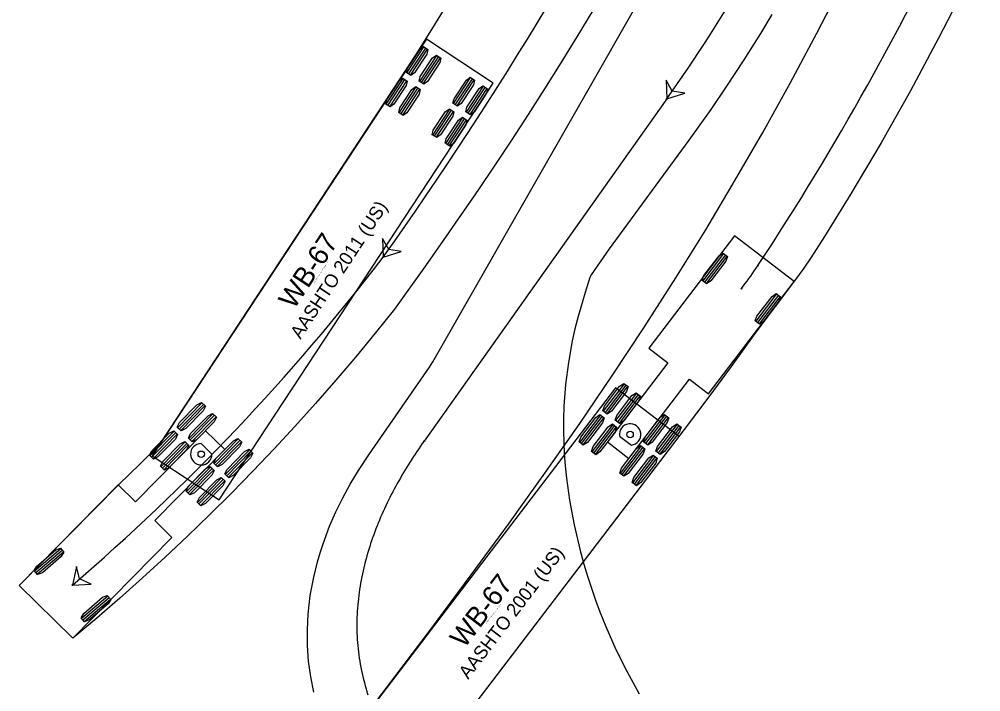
# Model space of a CAD drawing. Extents: x 2175591 to 2194071, y 76570 to 86955.
# Drawn here: x 2192827.4 to 2192929.6, y 86431.1 to 86502.5 of the extents above; entities that cross this region are included whole.
import ezdxf

# ---------------------------------------------------------------- set-up
doc = ezdxf.new("R2010")
doc.units = 0
doc.layers.add('-NOPLT', color=7, linetype='Continuous')
doc.layers.add('C-UTIL-STRM-TEXT', color=7, linetype='Continuous')

msp = doc.modelspace()

# ---------------------------------------------------------------- linework, layer by layer
at = {"layer": '-NOPLT'}
for p, q in [((2192870.68, 86500.42), (2192841.55, 86456.15)), ((2192868.59, 86496.83), (2192870.41, 86499.59)), ((2192877.78, 86495.75), (2192870.68, 86500.42)), ((2192868.78, 86496.71), (2192870.6, 86499.46)), ((2192868.98, 86496.58), (2192870.79, 86499.34)), ((2192869.97, 86495.92), (2192871.79, 86498.68)), ((2192870.16, 86495.8), (2192871.98, 86498.56)), ((2192870.35, 86495.67), (2192872.17, 86498.43)), ((2192848.65, 86451.48), (2192877.78, 86495.75)), ((2192866.39, 86493.49), (2192868.21, 86496.25)), ((2192866.59, 86493.36), (2192868.4, 86496.12)), ((2192866.78, 86493.24), (2192868.59, 86496)), ((2192873.55, 86493.57), (2192875.36, 86496.33)), ((2192873.74, 86493.44), (2192875.56, 86496.2)), ((2192873.93, 86493.32), (2192875.75, 86496.08)), ((2192874.93, 86492.66), (2192876.74, 86495.42)), ((2192867.77, 86492.58), (2192869.59, 86495.34)), ((2192867.96, 86492.46), (2192869.78, 86495.21)), ((2192868.16, 86492.33), (2192869.97, 86495.09)), ((2192875.12, 86492.54), (2192876.93, 86495.29)), ((2192875.31, 86492.41), (2192877.13, 86495.17)), ((2192896.22, 86494.08), (2192870.43, 86457.71)), ((2192871.35, 86490.23), (2192873.17, 86492.99)), ((2192871.54, 86490.1), (2192873.36, 86492.86)), ((2192871.73, 86489.98), (2192873.55, 86492.73)), ((2192872.73, 86489.32), (2192874.54, 86492.08)), ((2192872.92, 86489.2), (2192874.73, 86491.95)), ((2192873.11, 86489.07), (2192874.93, 86491.83)), ((2192844.25, 86459.15), (2192846.82, 86461.77)), ((2192844.41, 86458.99), (2192846.99, 86461.61)), ((2192844.58, 86458.83), (2192847.15, 86461.45)), ((2192845.43, 86458), (2192848, 86460.61)), ((2192845.59, 86457.84), (2192848.16, 86460.45)), ((2192845.75, 86457.68), (2192848.33, 86460.29)), ((2192847.2, 86458.82), (2192839.77, 86451.27)), ((2192841.3, 86456.16), (2192843.88, 86458.77)), ((2192849.25, 86456.81), (2192847.2, 86458.82)), ((2192841.47, 86456), (2192844.04, 86458.61)), ((2192841.63, 86455.84), (2192844.2, 86458.45)), ((2192842.48, 86455), (2192845.05, 86457.62)), ((2192848.12, 86455.34), (2192850.69, 86457.96)), ((2192848.29, 86455.18), (2192850.86, 86457.79)), ((2192848.45, 86455.02), (2192851.02, 86457.63)), ((2192841.81, 86449.26), (2192849.25, 86456.81)), ((2192842.64, 86454.84), (2192845.22, 86457.46)), ((2192842.81, 86454.68), (2192845.38, 86457.3)), ((2192847.89, 86456.33), (2192846.74, 86457.46)), ((2192849.3, 86454.18), (2192851.87, 86456.8)), ((2192849.46, 86454.02), (2192852.03, 86456.64)), ((2192841.55, 86456.15), (2192848.65, 86451.48)), ((2192849.62, 86453.86), (2192852.2, 86456.48)), ((2192845.18, 86452.35), (2192847.75, 86454.96)), ((2192845.34, 86452.19), (2192847.91, 86454.8)), ((2192845.5, 86452.03), (2192848.07, 86454.64)), ((2192846.35, 86451.19), (2192848.92, 86453.8)), ((2192846.51, 86451.03), (2192849.09, 86453.64)), ((2192837.94, 86453.07), (2192827.41, 86442.38)), ((2192839.77, 86451.27), (2192837.94, 86453.07)), ((2192846.68, 86450.87), (2192849.25, 86453.48)), ((2192848.65, 86451.48), (2192848.65, 86451.48)), ((2192843.64, 86447.46), (2192841.81, 86449.26)), ((2192833.11, 86436.77), (2192843.64, 86447.46)), ((2192829.03, 86443.92), (2192831.82, 86446.3)), ((2192829.18, 86443.74), (2192831.97, 86446.13)), ((2192829.33, 86443.57), (2192832.12, 86445.95)), ((2192827.41, 86442.38), (2192833.11, 86436.77)), ((2192834.02, 86438.89), (2192836.81, 86441.28)), ((2192834.17, 86438.72), (2192836.96, 86441.11)), ((2192834.32, 86438.55), (2192837.11, 86440.93)), ((2192833.11, 86436.77), (2192833.11, 86436.77))]:
    msp.add_line(p, q, dxfattribs=at)
for points in [[(2192858.7, 86431.03), (2192858.38, 86432.67), (2192858.16, 86434.32), (2192858.04, 86435.98), (2192858.03, 86437.65), (2192858.11, 86439.31), (2192858.21, 86440.31), (2192858.34, 86441.3), (2192858.7, 86443.26), (2192859.1, 86444.88), (2192859.38, 86445.84), (2192859.69, 86446.79), (2192860.39, 86448.66), (2192861.06, 86450.19), (2192861.79, 86451.69), (2192862.59, 86453.15), (2192863.45, 86454.58), (2192864.55, 86456.25), (2192871, 86465.57), (2192871.35, 86466.14), (2192896.64, 86510.42)], [(2192888.35, 86503.45), (2192886.66, 86500.67), (2192884.96, 86497.9), (2192883.23, 86495.15), (2192881.48, 86492.41), (2192879.71, 86489.68), (2192877.89, 86486.93), (2192876.2, 86484.45), (2192872.46, 86479.03), (2192870.59, 86476.34), (2192867.29, 86471.72), (2192865.25, 86469.17), (2192863.17, 86466.66), (2192861.05, 86464.17), (2192858.9, 86461.71), (2192856.71, 86459.28), (2192854.49, 86456.89), (2192852.24, 86454.52), (2192849.96, 86452.19), (2192847.64, 86449.88), (2192845.3, 86447.61), (2192842.92, 86445.38), (2192840.52, 86443.18), (2192838.09, 86441.02), (2192835.65, 86438.91), (2192833.11, 86436.77), (2192827.41, 86442.38), (2192837.98, 86453.11), (2192840.26, 86455.28), (2192842.22, 86457.21), (2192842.46, 86457.52), (2192869.6, 86498.8), (2192871.26, 86501.43), (2192872.89, 86504.08)], [(2192907.38, 86503.03), (2192906.18, 86501.03), (2192904.41, 86498.21), (2192902.58, 86495.42), (2192900.89, 86492.94), (2192898.57, 86489.68), (2192890.1, 86478.12), (2192888.2, 86475.38), (2192888.05, 86475.09), (2192887.53, 86473.5), (2192886.79, 86470.94), (2192886.46, 86469.65), (2192886.17, 86468.35), (2192885.76, 86466.05), (2192885.46, 86463.74), (2192885.28, 86461.41), (2192885.24, 86460.08), (2192885.23, 86458.75), (2192885.32, 86456.41), (2192885.41, 86455.08), (2192885.55, 86453.76), (2192885.87, 86451.45), (2192886.36, 86448.83), (2192886.98, 86446.23), (2192887.42, 86444.63), (2192887.81, 86443.35), (2192888.66, 86440.82), (2192889.12, 86439.57), (2192889.74, 86438.03), (2192890.82, 86435.59), (2192892, 86433.2), (2192893.29, 86430.86)], [(2192896.22, 86494.08), (2192898.13, 86494.67), (2192896.8, 86494.89), (2192896.15, 86496.07), (2192896.22, 86494.08)], [(2192870.43, 86457.71), (2192870.24, 86457.44), (2192870.05, 86457.17), (2192869.86, 86456.89), (2192869.67, 86456.62), (2192869.49, 86456.34), (2192869.31, 86456.06), (2192869.13, 86455.78), (2192868.95, 86455.5), (2192868.77, 86455.22), (2192868.59, 86454.93), (2192868.42, 86454.65), (2192868.25, 86454.36), (2192868.08, 86454.08), (2192867.91, 86453.79), (2192867.75, 86453.5), (2192867.58, 86453.21), (2192867.42, 86452.91), (2192867.26, 86452.62), (2192867.11, 86452.33), (2192866.95, 86452.03), (2192866.8, 86451.73), (2192866.65, 86451.44), (2192866.51, 86451.14), (2192866.36, 86450.84), (2192866.22, 86450.53), (2192866.08, 86450.23), (2192865.95, 86449.93), (2192865.81, 86449.62), (2192865.68, 86449.31), (2192865.56, 86449.01), (2192865.43, 86448.7), (2192865.31, 86448.39), (2192865.19, 86448.08), (2192865.08, 86447.76), (2192864.96, 86447.45), (2192864.85, 86447.13), (2192864.75, 86446.82), (2192864.65, 86446.5), (2192864.55, 86446.18), (2192864.45, 86445.86), (2192864.36, 86445.54), (2192864.27, 86445.22), (2192864.18, 86444.9), (2192864.1, 86444.58), (2192864.02, 86444.25), (2192863.95, 86443.93), (2192863.88, 86443.6), (2192863.81, 86443.28), (2192863.75, 86442.95), (2192863.69, 86442.62), (2192863.63, 86442.29), (2192863.58, 86441.96), (2192863.53, 86441.63), (2192863.49, 86441.3), (2192863.45, 86440.97), (2192863.41, 86440.64), (2192863.38, 86440.31), (2192863.35, 86439.98), (2192863.33, 86439.64), (2192863.31, 86439.31), (2192863.3, 86438.98), (2192863.29, 86438.64), (2192863.29, 86438.31), (2192863.29, 86437.98), (2192863.29, 86437.64), (2192863.3, 86437.31), (2192863.31, 86436.98), (2192863.33, 86436.64), (2192863.35, 86436.31), (2192863.38, 86435.98), (2192863.41, 86435.65), (2192863.45, 86435.32), (2192863.49, 86434.99), (2192863.54, 86434.66), (2192863.59, 86434.33), (2192863.65, 86434), (2192863.71, 86433.67), (2192863.78, 86433.34), (2192863.85, 86433.02), (2192863.92, 86432.69), (2192864.01, 86432.37), (2192864.09, 86432.05), (2192864.18, 86431.73), (2192864.27, 86431.41), (2192864.36, 86431.09), (2192864.46, 86430.77)]]:
    msp.add_lwpolyline(points, dxfattribs=at)
for points in [[(2192869.02, 86496.55), (2192868.55, 86496.86), (2192868.66, 86497.34), (2192869.96, 86499.33), (2192870.36, 86499.62), (2192870.84, 86499.31), (2192870.73, 86498.82), (2192869.42, 86496.84)], [(2192870.4, 86495.64), (2192869.92, 86495.96), (2192870.03, 86496.44), (2192871.34, 86498.42), (2192871.74, 86498.71), (2192872.22, 86498.4), (2192872.11, 86497.92), (2192870.8, 86495.93)], [(2192866.82, 86493.21), (2192866.35, 86493.52), (2192866.46, 86494), (2192867.76, 86495.99), (2192868.16, 86496.28), (2192868.64, 86495.96), (2192868.53, 86495.48), (2192867.22, 86493.5)], [(2192873.98, 86493.29), (2192873.5, 86493.6), (2192873.61, 86494.08), (2192874.92, 86496.07), (2192875.32, 86496.36), (2192875.79, 86496.04), (2192875.68, 86495.56), (2192874.38, 86493.58)], [(2192875.36, 86492.38), (2192874.88, 86492.69), (2192874.99, 86493.18), (2192876.3, 86495.16), (2192876.69, 86495.45), (2192877.17, 86495.14), (2192877.06, 86494.66), (2192875.76, 86492.67)], [(2192896.22, 86494.08), (2192898.13, 86494.67), (2192896.8, 86494.89), (2192896.15, 86496.07)], [(2192868.2, 86492.3), (2192867.73, 86492.61), (2192867.84, 86493.1), (2192869.14, 86495.08), (2192869.54, 86495.37), (2192870.02, 86495.06), (2192869.91, 86494.58), (2192868.6, 86492.59)], [(2192871.78, 86489.95), (2192871.3, 86490.26), (2192871.41, 86490.74), (2192872.72, 86492.73), (2192873.12, 86493.02), (2192873.6, 86492.7), (2192873.49, 86492.22), (2192872.18, 86490.24)], [(2192873.16, 86489.04), (2192872.68, 86489.35), (2192872.79, 86489.83), (2192874.1, 86491.82), (2192874.5, 86492.11), (2192874.97, 86491.8), (2192874.86, 86491.32), (2192873.56, 86489.33)], [(2192866.09, 86477.25), (2192868, 86477.84), (2192866.67, 86478.07), (2192866.02, 86479.25)], [(2192844.62, 86458.79), (2192844.21, 86459.19), (2192844.45, 86459.68), (2192846.3, 86461.56), (2192846.78, 86461.81), (2192847.19, 86461.41), (2192846.95, 86460.92), (2192845.1, 86459.04)], [(2192845.79, 86457.64), (2192845.39, 86458.04), (2192845.62, 86458.52), (2192847.48, 86460.4), (2192847.96, 86460.65), (2192848.37, 86460.25), (2192848.13, 86459.76), (2192846.28, 86457.88)], [(2192841.67, 86455.8), (2192841.26, 86456.2), (2192841.5, 86456.69), (2192843.35, 86458.57), (2192843.84, 86458.81), (2192844.24, 86458.41), (2192844.01, 86457.93), (2192842.15, 86456.05)], [(2192842.85, 86454.64), (2192842.44, 86455.04), (2192842.68, 86455.53), (2192844.53, 86457.41), (2192845.01, 86457.66), (2192845.42, 86457.26), (2192845.18, 86456.77), (2192843.33, 86454.89)], [(2192848.49, 86454.98), (2192848.08, 86455.38), (2192848.32, 86455.87), (2192850.17, 86457.75), (2192850.65, 86458), (2192851.06, 86457.59), (2192850.82, 86457.11), (2192848.97, 86455.23)], [(2192849.67, 86453.82), (2192849.26, 86454.22), (2192849.49, 86454.71), (2192851.35, 86456.59), (2192851.83, 86456.84), (2192852.24, 86456.44), (2192852, 86455.95), (2192850.15, 86454.07)], [(2192845.54, 86451.99), (2192845.14, 86452.39), (2192845.37, 86452.88), (2192847.22, 86454.76), (2192847.71, 86455), (2192848.12, 86454.6), (2192847.88, 86454.11), (2192846.03, 86452.23)], [(2192846.72, 86450.83), (2192846.31, 86451.23), (2192846.55, 86451.72), (2192848.4, 86453.6), (2192848.88, 86453.84), (2192849.29, 86453.44), (2192849.05, 86452.96), (2192847.2, 86451.08)], [(2192829.37, 86443.53), (2192828.99, 86443.96), (2192829.27, 86444.43), (2192831.28, 86446.14), (2192831.78, 86446.34), (2192832.15, 86445.91), (2192831.88, 86445.44), (2192829.87, 86443.73)], [(2192833.07, 86442.42), (2192835.07, 86442.53), (2192833.83, 86443.07), (2192833.48, 86444.38)], [(2192834.36, 86438.5), (2192833.99, 86438.94), (2192834.26, 86439.4), (2192836.27, 86441.12), (2192836.77, 86441.32), (2192837.14, 86440.89), (2192836.86, 86440.42), (2192834.86, 86438.71)]]:
    msp.add_lwpolyline(points, close=True, dxfattribs=at)
for centre, radius in [((2192896.22, 86494.08), 0.0417), ((2192896.22, 86494.08), 0.0417), ((2192866.09, 86477.25), 0.0417), ((2192866.09, 86477.25), 0.0417), ((2192870.43, 86457.71), 0.0417), ((2192870.43, 86457.71), 0.0417), ((2192846.75, 86456.32), 0.34), ((2192833.07, 86442.42), 0.0417)]:
    msp.add_circle(centre, radius, dxfattribs=at)
for centre, radius, start, end in [((2192518.8, 86723.56), 425.77, 324.656, 333.1974), ((2192758.86, 86591.64), 168.49, 324.6149, 330.0297), ((2192682.44, 86618.31), 231.57, 310.5753, 322.4721), ((2192846.75, 86456.32), 1.14, 90.4434, 0.4434)]:
    msp.add_arc(centre, radius, start, end, dxfattribs=at)
at = {"layer": 'C-UTIL-STRM-TEXT'}
for p, q in [((2192903.4, 86479.52), (2192894.3, 86467.59)), ((2192909.76, 86474.66), (2192903.4, 86479.52)), ((2192903.4, 86479.52), (2192903.4, 86479.52)), ((2192902.26, 86477.65), (2192900.04, 86474.74)), ((2192902.45, 86477.51), (2192900.22, 86474.6)), ((2192902.63, 86477.38), (2192900.4, 86474.46)), ((2192900.66, 86462.74), (2192909.76, 86474.66)), ((2192907.89, 86473.36), (2192905.67, 86470.44)), ((2192908.08, 86473.22), (2192905.85, 86470.3)), ((2192908.26, 86473.08), (2192906.03, 86470.16)), ((2192894.3, 86467.59), (2192896.34, 86466.03)), ((2192896.34, 86466.03), (2192889.92, 86457.62)), ((2192891.7, 86463.81), (2192889.47, 86460.89)), ((2192892.19, 86455.88), (2192898.62, 86464.29)), ((2192898.62, 86464.29), (2192900.66, 86462.74)), ((2192890.76, 86463.37), (2192858.61, 86421.24)), ((2192891.88, 86463.67), (2192889.66, 86460.75)), ((2192892.06, 86463.53), (2192889.84, 86460.62)), ((2192897.52, 86458.21), (2192890.76, 86463.37)), ((2192890.76, 86463.37), (2192890.76, 86463.37)), ((2192893.01, 86462.81), (2192890.78, 86459.89)), ((2192893.19, 86462.67), (2192890.97, 86459.75)), ((2192893.37, 86462.53), (2192891.15, 86459.61)), ((2192889.17, 86460.5), (2192886.95, 86457.58)), ((2192889.35, 86460.36), (2192887.13, 86457.44)), ((2192889.53, 86460.22), (2192887.31, 86457.3)), ((2192896.02, 86460.51), (2192893.79, 86457.6)), ((2192896.2, 86460.37), (2192893.97, 86457.46)), ((2192896.38, 86460.23), (2192894.16, 86457.32)), ((2192890.48, 86459.49), (2192888.26, 86456.58)), ((2192890.66, 86459.36), (2192888.44, 86456.44)), ((2192890.85, 86459.22), (2192888.62, 86456.3)), ((2192897.33, 86459.51), (2192895.1, 86456.6)), ((2192897.51, 86459.37), (2192895.29, 86456.46)), ((2192897.69, 86459.23), (2192895.47, 86456.32)), ((2192865.36, 86416.08), (2192897.52, 86458.21)), ((2192889.92, 86457.62), (2192892.19, 86455.88)), ((2192891.19, 86458.25), (2192892.47, 86457.27)), ((2192893.49, 86457.2), (2192891.26, 86454.28)), ((2192893.67, 86457.06), (2192891.45, 86454.15)), ((2192893.85, 86456.92), (2192891.63, 86454.01)), ((2192894.8, 86456.2), (2192892.58, 86453.28)), ((2192894.98, 86456.06), (2192892.76, 86453.14)), ((2192895.17, 86455.92), (2192892.94, 86453.01))]:
    msp.add_line(p, q, dxfattribs=at)
for points in [[(2192861.46, 86419.09), (2192858.81, 86421.11), (2192858.76, 86421.44), (2192866.44, 86431.51), (2192871.07, 86437.62), (2192875.45, 86443.5), (2192879.39, 86448.88), (2192883.27, 86454.3), (2192886.9, 86459.49), (2192890.46, 86464.72), (2192893.77, 86469.73), (2192897.19, 86475.06), (2192900.35, 86480.16), (2192903.43, 86485.31), (2192906.42, 86490.51), (2192909.34, 86495.75), (2192912.16, 86501.05), (2192914.74, 86506.09)], [(2192927.99, 86506.14), (2192925.1, 86500.51), (2192922.1, 86494.93), (2192918.99, 86489.41), (2192915.76, 86483.97), (2192912.96, 86479.43), (2192911.53, 86477.18), (2192910.79, 86476.07), (2192909.8, 86474.73), (2192905.56, 86469.16), (2192903.05, 86465.63), (2192900.68, 86462.41), (2192898.08, 86458.95), (2192865.53, 86416.3), (2192864.91, 86416.47), (2192861.46, 86419.09)], [(2192904.15, 86473.91), (2192904.35, 86474.17), (2192904.55, 86474.44), (2192904.75, 86474.71), (2192904.95, 86474.98), (2192905.14, 86475.25), (2192905.33, 86475.52), (2192905.52, 86475.8), (2192905.71, 86476.07), (2192905.89, 86476.35)]]:
    msp.add_lwpolyline(points, dxfattribs=at)
for points in [[(2192902.22, 86477.69), (2192902.67, 86477.34), (2192902.5, 86476.83), (2192900.9, 86474.73), (2192900.45, 86474.43), (2192899.99, 86474.77), (2192900.17, 86475.29), (2192901.77, 86477.38)], [(2192907.85, 86473.39), (2192908.3, 86473.04), (2192908.13, 86472.53), (2192906.53, 86470.43), (2192906.08, 86470.13), (2192905.62, 86470.48), (2192905.8, 86470.99), (2192907.4, 86473.09)], [(2192891.65, 86463.84), (2192892.11, 86463.5), (2192891.93, 86462.98), (2192890.33, 86460.88), (2192889.88, 86460.58), (2192889.43, 86460.93), (2192889.6, 86461.44), (2192891.2, 86463.54)], [(2192892.96, 86462.84), (2192893.42, 86462.49), (2192893.24, 86461.98), (2192891.64, 86459.88), (2192891.19, 86459.58), (2192890.74, 86459.93), (2192890.91, 86460.44), (2192892.52, 86462.54)], [(2192889.12, 86460.53), (2192889.58, 86460.18), (2192889.4, 86459.67), (2192887.8, 86457.57), (2192887.35, 86457.27), (2192886.9, 86457.62), (2192887.07, 86458.13), (2192888.68, 86460.23)], [(2192895.97, 86460.55), (2192896.43, 86460.2), (2192896.25, 86459.69), (2192894.65, 86457.59), (2192894.2, 86457.28), (2192893.75, 86457.63), (2192893.92, 86458.14), (2192895.52, 86460.24)], [(2192890.44, 86459.53), (2192890.89, 86459.18), (2192890.72, 86458.67), (2192889.11, 86456.57), (2192888.67, 86456.27), (2192888.21, 86456.61), (2192888.39, 86457.13), (2192889.99, 86459.23)], [(2192897.28, 86459.55), (2192897.74, 86459.2), (2192897.56, 86458.69), (2192895.96, 86456.59), (2192895.51, 86456.28), (2192895.06, 86456.63), (2192895.23, 86457.14), (2192896.83, 86459.24)], [(2192893.44, 86457.23), (2192893.9, 86456.89), (2192893.72, 86456.37), (2192892.12, 86454.28), (2192891.67, 86453.97), (2192891.22, 86454.32), (2192891.39, 86454.83), (2192893, 86456.93)], [(2192894.76, 86456.23), (2192895.21, 86455.89), (2192895.04, 86455.37), (2192893.43, 86453.27), (2192892.99, 86452.97), (2192892.53, 86453.32), (2192892.71, 86453.83), (2192894.31, 86455.93)]]:
    msp.add_lwpolyline(points, close=True, dxfattribs=at)
for centre, radius in [((2192905.89, 86476.35), 0.0417), ((2192905.89, 86476.35), 0.0417), ((2192904.15, 86473.91), 0.0417), ((2192892.32, 86458.41), 0.34)]:
    msp.add_circle(centre, radius, dxfattribs=at)
for centre, radius, start, end in [((2192651.95, 86643.85), 304.21, 326.5918, 343.5286), ((2192892.32, 86458.41), 1.14, 277.6518, 187.6518)]:
    msp.add_arc(centre, radius, start, end, dxfattribs=at)

# ---------------------------------------------------------------- texts
at = {"layer": '-NOPLT'}
for s, height, p in [('AASHTO 2011 (US)', 1.4167, (2192857.29, 86468.46)), ('WB-67', 2.125, (2192856.61, 86471.61)), ('(c) 2019 Transoft Solutions, Inc. All rights reserved.', 0.085, (2192858.75, 86474.48))]:
    msp.add_text(s, height=height, rotation=56.6568, dxfattribs=at).set_placement(p)
at = {"layer": 'C-UTIL-STRM-TEXT'}
for s, height, p in [('AASHTO 2001 (US)', 1.4167, (2192875.11, 86432.34)), ('WB-67', 2.125, (2192874.7, 86435.61)), ('(c) 2024 Transoft Solutions, Inc. All rights reserved.', 0.085, (2192877.04, 86438.32))]:
    msp.add_text(s, height=height, rotation=52.6518, dxfattribs=at).set_placement(p)

doc.saveas('drawing.dxf')
